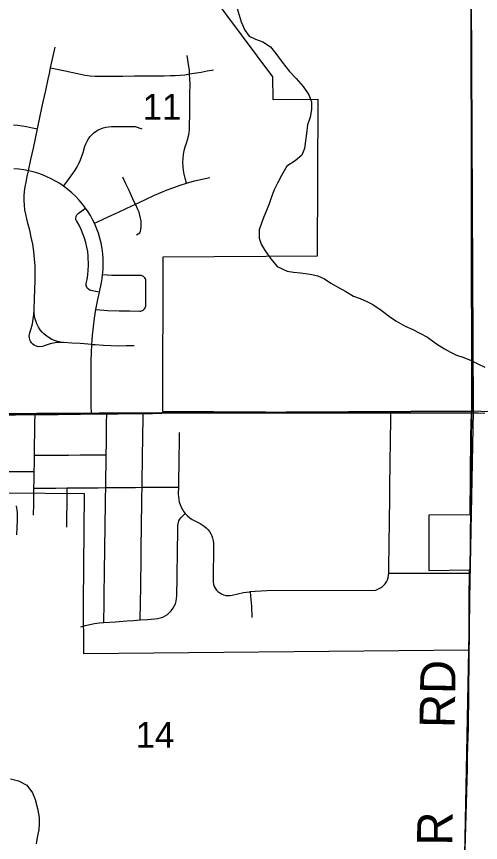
# Model space of a CAD drawing. Extents: x -11.1 to 34, y -3.9 to 22.
# Drawn here: x 5.641 to 6.389, y 15.573 to 16.906 of the extents above; entities that cross this region are included whole.
import ezdxf

# ---------------------------------------------------------------- set-up
doc = ezdxf.new("R2010")
doc.units = 0
for name, color, linetype in [('GM_X_City_Street', 7, 'Continuous'), ('GM_X_Corporation', 7, 'Continuous'), ('GM_X_Minor_River', 7, 'Continuous'), ('GM_X_Section_Text', 7, 'Continuous'), ('GM_X_State_Route', 7, 'Continuous'), ('GM_X_Township_Road', 7, 'Continuous'), ('GM_X_Township_Road_Text', 7, 'Continuous')]:
    doc.layers.add(name, color=color, linetype=linetype)

msp = doc.modelspace()

# ---------------------------------------------------------------- linework, layer by layer
at = {"layer": 'GM_X_City_Street'}
for points in [[(5.7623, 16.3768), (5.7437, 16.3781), (5.7302, 16.379), (5.7166, 16.3799), (5.7118, 16.3805), (5.707, 16.3815), (5.7023, 16.383), (5.6978, 16.3849), (5.6935, 16.3872), (5.6895, 16.39), (5.6857, 16.3931), (5.6823, 16.3965), (5.6792, 16.4003), (5.6765, 16.4044), (5.6742, 16.4087), (5.6723, 16.4132), (5.6708, 16.4179), (5.6698, 16.4226), (5.6693, 16.4275), (5.6692, 16.4324), (5.6699, 16.451), (5.6704, 16.4656), (5.6709, 16.4802), (5.6711, 16.4919), (5.6708, 16.5036), (5.67, 16.5152), (5.6687, 16.5269), (5.667, 16.5384), (5.6647, 16.5499), (5.6621, 16.5613), (5.6597, 16.5705), (5.6573, 16.5797), (5.6557, 16.5869), (5.6545, 16.5943), (5.6537, 16.6017), (5.6533, 16.6091), (5.6534, 16.6165), (5.6539, 16.6239), (5.6548, 16.6313), (5.6562, 16.6386), (5.6582, 16.6479), (5.6602, 16.6572), (5.6641, 16.6754), (5.668, 16.6936), (5.6713, 16.7092), (5.6747, 16.7247), (5.6786, 16.743), (5.6814, 16.7558), (5.6841, 16.7685), (5.688, 16.7868), (5.692, 16.805), (5.694, 16.8142), (5.6959, 16.8235), (5.6995, 16.84), (5.7031, 16.8566)], [(5.9152, 16.6371), (5.9131, 16.6451), (5.9115, 16.6514), (5.9104, 16.6577), (5.9096, 16.6641), (5.9094, 16.6705), (5.9096, 16.6769), (5.9103, 16.6833), (5.9114, 16.6896), (5.913, 16.6958), (5.915, 16.7019), (5.9168, 16.7073), (5.9183, 16.7128), (5.9193, 16.7184), (5.9199, 16.724), (5.9202, 16.7297), (5.9204, 16.7484), (5.9205, 16.767), (5.9207, 16.782), (5.9208, 16.7969), (5.9207, 16.8052), (5.9202, 16.8134), (5.9197, 16.8194), (5.9189, 16.8253), (5.9164, 16.8433)], [(5.6959, 16.8235), (5.7013, 16.8223), (5.7196, 16.8184), (5.7318, 16.8157), (5.7441, 16.8131), (5.7518, 16.8117), (5.7596, 16.8106), (5.7675, 16.81), (5.7753, 16.8099), (5.794, 16.81), (5.8126, 16.8101), (5.8313, 16.8103), (5.8499, 16.8104), (5.8685, 16.8105), (5.8788, 16.8106), (5.8892, 16.8107), (5.897, 16.8109), (5.9047, 16.8114), (5.9125, 16.8122), (5.9202, 16.8134), (5.9386, 16.8165), (5.9486, 16.8182), (5.9586, 16.8198)], [(5.636, 16.7312), (5.6431, 16.7307), (5.6501, 16.7298), (5.657, 16.7286), (5.6664, 16.7265), (5.6747, 16.7247)], [(5.7169, 16.632), (5.722, 16.6391), (5.7318, 16.6528), (5.7353, 16.658), (5.7385, 16.6634), (5.7414, 16.6689), (5.744, 16.6746), (5.7463, 16.6805), (5.7482, 16.6864), (5.7513, 16.6966), (5.7527, 16.7007), (5.7546, 16.7047), (5.7568, 16.7085), (5.7594, 16.712), (5.7623, 16.7153), (5.7656, 16.7182), (5.7691, 16.7209), (5.7728, 16.7231), (5.7768, 16.725), (5.7809, 16.7265), (5.7852, 16.7276), (5.7895, 16.7283), (5.7939, 16.7286), (5.8125, 16.7287), (5.8225, 16.7288), (5.8325, 16.7288), (5.8432, 16.7247)], [(5.7616, 16.2645), (5.7615, 16.2788), (5.7614, 16.2974), (5.7613, 16.3161), (5.7612, 16.3264), (5.7611, 16.3367), (5.7612, 16.3501), (5.7616, 16.3635), (5.7623, 16.3768), (5.7634, 16.391), (5.7649, 16.4052), (5.7668, 16.4193), (5.769, 16.4331), (5.7721, 16.4492), (5.7745, 16.4612), (5.7778, 16.477), (5.7789, 16.4831), (5.7797, 16.4889), (5.7805, 16.4977), (5.7809, 16.5062), (5.7807, 16.5147), (5.7801, 16.5232), (5.779, 16.5316), (5.7774, 16.54), (5.7754, 16.5483), (5.7729, 16.5564), (5.77, 16.5644), (5.7666, 16.5723), (5.7634, 16.5786), (5.76, 16.5848), (5.7563, 16.5909), (5.7523, 16.5968), (5.7472, 16.6034), (5.7418, 16.6098), (5.7361, 16.6159), (5.73, 16.6216), (5.7236, 16.627), (5.7169, 16.632), (5.7105, 16.6364), (5.7038, 16.6405), (5.6969, 16.6442), (5.6898, 16.6475), (5.6826, 16.6505), (5.6752, 16.6531), (5.6678, 16.6553), (5.6602, 16.6572), (5.6524, 16.6586), (5.6445, 16.6597), (5.6366, 16.6603)], [(5.7666, 16.5723), (5.7716, 16.5746), (5.7885, 16.5825), (5.8054, 16.5903), (5.819, 16.5967), (5.8327, 16.6031), (5.8481, 16.6103), (5.8636, 16.6175), (5.8737, 16.622), (5.884, 16.6263), (5.8944, 16.6302), (5.9049, 16.6339), (5.9152, 16.6371), (5.9278, 16.6407), (5.9402, 16.6438), (5.9527, 16.6464)], [(5.8327, 16.6031), (5.8303, 16.6082), (5.8224, 16.6251), (5.8173, 16.636), (5.8123, 16.6468)], [(5.8346, 16.5539), (5.8397, 16.5567), (5.8409, 16.5597), (5.8413, 16.5617), (5.8419, 16.5665), (5.842, 16.5713), (5.8417, 16.5761), (5.8411, 16.5808), (5.84, 16.5855), (5.8385, 16.5901), (5.8367, 16.5945), (5.8327, 16.6031)], [(5.7745, 16.4612), (5.7663, 16.4629), (5.7606, 16.4641), (5.759, 16.4646), (5.7576, 16.4653), (5.7562, 16.4663), (5.7551, 16.4675), (5.7542, 16.4689), (5.7535, 16.4704), (5.7532, 16.472), (5.7531, 16.4736), (5.7533, 16.4753), (5.7546, 16.4818), (5.7559, 16.4892), (5.7567, 16.4966), (5.7572, 16.5041), (5.7567, 16.5191), (5.7558, 16.5266), (5.7545, 16.5339), (5.7528, 16.5412), (5.7506, 16.5484), (5.748, 16.5555), (5.7451, 16.5624), (5.7417, 16.5691), (5.7379, 16.5756), (5.7372, 16.577), (5.7367, 16.5785), (5.7365, 16.5801), (5.7369, 16.5832), (5.7375, 16.5847), (5.7383, 16.5861), (5.7393, 16.5873), (5.7405, 16.5883), (5.7484, 16.594), (5.7523, 16.5968)], [(5.769, 16.4331), (5.7753, 16.4325), (5.7816, 16.4319), (5.7879, 16.4316), (5.8065, 16.4312), (5.8231, 16.4309), (5.8397, 16.4306), (5.8412, 16.4307), (5.8427, 16.431), (5.8441, 16.4316), (5.8454, 16.4323), (5.8465, 16.4333), (5.8475, 16.4344), (5.8483, 16.4357), (5.8489, 16.437), (5.8493, 16.4385), (5.8494, 16.44), (5.8496, 16.4586), (5.8496, 16.4686), (5.8497, 16.4786), (5.8496, 16.4801), (5.8493, 16.4815), (5.8487, 16.4829), (5.8479, 16.4842), (5.847, 16.4853), (5.8458, 16.4863), (5.8446, 16.4871), (5.8432, 16.4877), (5.8417, 16.488), (5.8402, 16.4881), (5.8216, 16.488), (5.8021, 16.4879), (5.7947, 16.488), (5.7872, 16.4884), (5.7797, 16.4889)], [(5.7166, 16.3799), (5.7113, 16.38), (5.706, 16.3798), (5.7007, 16.379), (5.6954, 16.3779), (5.6903, 16.3763), (5.6854, 16.3744), (5.6827, 16.3735), (5.6771, 16.373), (5.6743, 16.3734), (5.6717, 16.3744), (5.6692, 16.3757), (5.667, 16.3774), (5.665, 16.3795), (5.6635, 16.3819), (5.6624, 16.3844), (5.6617, 16.3872), (5.6614, 16.39), (5.6617, 16.3928), (5.6624, 16.3955), (5.6646, 16.4027), (5.6664, 16.41), (5.6678, 16.4174), (5.6687, 16.4249), (5.6692, 16.4324)], [(5.7623, 16.3768), (5.7679, 16.3765), (5.7812, 16.3756), (5.7936, 16.3749), (5.806, 16.3746), (5.8184, 16.3749), (5.8308, 16.3751)], [(5.6698, 16.1978), (5.67, 16.2164), (5.6703, 16.2329), (5.6705, 16.2494), (5.6707, 16.2636)], [(5.7817, 15.928), (5.7818, 15.9373), (5.782, 15.9501), (5.7822, 15.9628), (5.7824, 15.9815), (5.7827, 16.0001), (5.783, 16.0187), (5.7832, 16.0374), (5.7835, 16.056), (5.7838, 16.0747), (5.784, 16.0933), (5.7843, 16.112), (5.7845, 16.1288), (5.7848, 16.1456), (5.785, 16.1643), (5.7853, 16.1815), (5.7855, 16.1986), (5.7858, 16.2173), (5.786, 16.2335), (5.7862, 16.2497), (5.7864, 16.2647)], [(5.8405, 15.932), (5.8406, 15.9402), (5.8407, 15.9517), (5.8409, 15.9633), (5.8412, 15.9819), (5.8414, 16.0005), (5.8417, 16.0192), (5.842, 16.0378), (5.8422, 16.0565), (5.8425, 16.0751), (5.8427, 16.0937), (5.843, 16.1124), (5.8432, 16.1292), (5.8435, 16.1461), (5.8437, 16.1647), (5.844, 16.1834), (5.8443, 16.202), (5.8445, 16.2206), (5.8447, 16.2355), (5.845, 16.2504), (5.8452, 16.2653)], [(5.9033, 16.2344), (5.903, 16.2157), (5.9027, 16.1977), (5.9025, 16.1796), (5.9022, 16.163), (5.902, 16.1464), (5.9018, 16.1351), (5.902, 16.1308), (5.9025, 16.1265), (5.9034, 16.1223), (5.9047, 16.1182), (5.9063, 16.1142), (5.9084, 16.1104), (5.9107, 16.1068), (5.913, 16.1039), (5.9167, 16.1), (5.9203, 16.0969), (5.9242, 16.0942), (5.9284, 16.0918), (5.9369, 16.0877), (5.9405, 16.0857), (5.9438, 16.0834), (5.9468, 16.0808), (5.9496, 16.0779), (5.9521, 16.0747), (5.9542, 16.0712), (5.9559, 16.0676), (5.9573, 16.0638), (5.9582, 16.0598), (5.9588, 16.0558), (5.9589, 16.0518), (5.9586, 16.0332), (5.9582, 16.0148), (5.9579, 15.9964), (5.9581, 15.993), (5.9587, 15.9895), (5.9599, 15.9862), (5.9615, 15.9831), (5.9635, 15.9803), (5.9659, 15.9778), (5.9687, 15.9756), (5.9717, 15.9739), (5.9749, 15.9726), (5.9783, 15.9717), (5.9818, 15.9714), (5.9853, 15.9715), (5.9887, 15.9722), (5.9979, 15.9743), (6.0072, 15.9761), (6.0165, 15.9775), (6.0181, 15.9777), (6.026, 15.9785), (6.0354, 15.9791), (6.0448, 15.9793), (6.2204, 15.9803), (6.2239, 15.9815), (6.2272, 15.9831), (6.2303, 15.9851), (6.2331, 15.9875), (6.2355, 15.9903), (6.2376, 15.9933), (6.2392, 15.9966), (6.2405, 16.0001), (6.2412, 16.0037), (6.2415, 16.0075), (6.2417, 16.0262), (6.242, 16.0448), (6.2422, 16.0635), (6.2424, 16.0821), (6.2427, 16.1007), (6.2429, 16.1194), (6.2431, 16.138), (6.2434, 16.1567), (6.2436, 16.1753), (6.2438, 16.194), (6.2441, 16.2126), (6.2443, 16.2312), (6.2445, 16.2457), (6.2446, 16.2602), (6.2447, 16.2663)], [(5.6694, 16.1718), (5.6696, 16.1848), (5.6698, 16.1978)], [(5.6698, 16.1978), (5.6875, 16.1979), (5.7062, 16.198), (5.7248, 16.1982), (5.7434, 16.1983), (5.7578, 16.1984), (5.7721, 16.1985), (5.7855, 16.1986)], [(5.2553, 16.1662), (5.2644, 16.1671), (5.283, 16.1684), (5.3016, 16.1696), (5.3202, 16.1709), (5.3376, 16.1721), (5.355, 16.1733), (5.3728, 16.1743), (5.4256, 16.1744), (5.4406, 16.1745), (5.4943, 16.1746), (5.513, 16.1746), (5.5316, 16.1747), (5.5502, 16.1747), (5.5689, 16.1747), (5.5875, 16.1748), (5.5992, 16.1748), (5.6109, 16.1748), (5.6233, 16.1715), (5.6382, 16.1716), (5.6531, 16.1717), (5.6694, 16.1718)], [(5.6684, 16.101), (5.6687, 16.1197), (5.6689, 16.1322), (5.669, 16.1448), (5.6692, 16.1583), (5.6694, 16.1718)], [(5.669, 16.1448), (5.6861, 16.1449), (5.7045, 16.145), (5.7228, 16.1452), (5.7415, 16.1453), (5.7601, 16.1455), (5.7724, 16.1455), (5.7848, 16.1456), (5.8034, 16.1458), (5.822, 16.1459), (5.8328, 16.146), (5.8435, 16.1461), (5.858, 16.1462), (5.8726, 16.1462), (5.8873, 16.1463), (5.902, 16.1464)], [(5.7219, 16.0817), (5.7222, 16.1003), (5.7224, 16.1178), (5.7227, 16.1352), (5.7228, 16.1452)], [(5.7448, 15.9208), (5.752, 15.923), (5.7593, 15.9248), (5.7667, 15.9262), (5.7742, 15.9273), (5.7817, 15.928), (5.8003, 15.9292), (5.8189, 15.9305), (5.8297, 15.9312), (5.8405, 15.932), (5.8523, 15.9328), (5.8642, 15.9336), (5.8685, 15.9341), (5.8727, 15.9352), (5.8768, 15.9367), (5.8807, 15.9386), (5.8843, 15.941), (5.8876, 15.9438), (5.8906, 15.9469), (5.8932, 15.9504), (5.8954, 15.9542), (5.8971, 15.9581), (5.8984, 15.9623), (5.8992, 15.9665), (5.8995, 15.9709), (5.8996, 15.9765), (5.8999, 15.9951), (5.9001, 16.0138), (5.9004, 16.0324), (5.9007, 16.051), (5.9009, 16.0678), (5.9011, 16.0845), (5.9014, 16.0872), (5.902, 16.0898), (5.9029, 16.0922), (5.9042, 16.0946), (5.9058, 16.0967), (5.9077, 16.0986), (5.913, 16.1039)], [(6.2415, 16.0075), (6.292, 16.0076), (6.3727, 16.0076)], [(6.0209, 15.9358), (6.0207, 15.9542), (6.0202, 15.9599), (6.019, 15.9702), (6.0181, 15.9777)]]:
    msp.add_lwpolyline(points, dxfattribs=at)
at = {"layer": 'GM_X_Corporation'}
for points in [[(5.385, 17.2762), (6.3727, 17.2765), (6.3775, 16.2691), (5.3715, 16.2638)], [(7.3791, 17.2313), (7.364, 16.2758), (7.3634, 16.2255), (6.3775, 16.2691), (6.3727, 17.2765)], [(5.3715, 16.2638), (6.3775, 16.2691), (6.3578, 15.2497), (5.3559, 15.2538)]]:
    msp.add_lwpolyline(points, close=True, dxfattribs=at)
msp.add_lwpolyline([(5.9275, 16.9789), (6.0538, 16.8089), (6.0542, 16.772), (6.1268, 16.7728), (6.1257, 16.5195), (5.8768, 16.5179), (5.8764, 16.2688), (6.3743, 16.2658), (6.3735, 16.2285), (6.3722, 16.1019), (6.3062, 16.1009), (6.3063, 16.0116), (6.3713, 16.0127), (6.3706, 15.962), (6.3705, 15.8833), (5.7496, 15.8773), (5.749, 15.9599), (5.7505, 16.1357), (5.6236, 16.1369)], dxfattribs=at)
at = {"layer": 'GM_X_Minor_River'}
for points in [[(5.9967, 16.9192), (6.0034, 16.8973), (6.0091, 16.8843), (6.0161, 16.8742), (6.0262, 16.8698), (6.0382, 16.8653), (6.0505, 16.8573), (6.059, 16.8465), (6.0696, 16.8325), (6.0814, 16.8174), (6.0921, 16.8061), (6.1031, 16.7929), (6.1126, 16.7797), (6.1169, 16.7682), (6.117, 16.756), (6.1144, 16.7439), (6.1103, 16.7311), (6.1088, 16.7171)], [(6.1088, 16.7171), (6.1073, 16.7057), (6.1055, 16.6932), (6.1014, 16.6823), (6.0906, 16.6731), (6.0771, 16.6643), (6.0683, 16.6493), (6.0619, 16.637), (6.0567, 16.6265), (6.0523, 16.6148), (6.0482, 16.6035), (6.0441, 16.593), (6.0401, 16.5828), (6.036, 16.5723), (6.0323, 16.5617), (6.0324, 16.5484), (6.0355, 16.5384), (6.0421, 16.528), (6.0509, 16.5152), (6.0615, 16.5024), (6.0773, 16.4951), (6.0879, 16.4933), (6.0992, 16.4923), (6.1147, 16.4904), (6.1272, 16.4874), (6.138, 16.4825), (6.1481, 16.4758), (6.1616, 16.4682), (6.1724, 16.4622), (6.1847, 16.4547), (6.1953, 16.451), (6.2058, 16.4462), (6.2159, 16.4413), (6.2293, 16.4322), (6.2427, 16.4216), (6.2528, 16.4149), (6.2677, 16.4065), (6.2805, 16.4009), (6.2917, 16.3952), (6.3037, 16.3885), (6.3186, 16.3778), (6.3313, 16.3699), (6.341, 16.3643), (6.3508, 16.3595), (6.3628, 16.3557), (6.3744, 16.3509), (6.3853, 16.3457), (6.3962, 16.34)], [(5.6405, 16.1164), (5.6417, 16.1057), (5.6421, 16.0935), (5.6415, 16.0814), (5.6408, 16.0696)], [(5.6314, 15.6757), (5.6442, 15.6723), (5.6573, 15.6651), (5.6669, 15.6531), (5.6712, 15.6423), (5.6749, 15.6274), (5.6772, 15.6133), (5.6774, 15.6034), (5.6767, 15.5932), (5.6741, 15.5807), (5.6727, 15.5708)]]:
    msp.add_lwpolyline(points, dxfattribs=at)
at = {"layer": 'GM_X_State_Route'}
for points in [[(5.5354, 16.2623), (5.554, 16.2624), (5.5685, 16.2626), (5.583, 16.2627), (5.6017, 16.2629), (5.6203, 16.2631), (5.639, 16.2633), (5.6548, 16.2634), (5.6707, 16.2636), (5.6894, 16.2638), (5.708, 16.2639), (5.7266, 16.2641), (5.7441, 16.2643), (5.7616, 16.2645), (5.774, 16.2646), (5.7864, 16.2647), (5.8051, 16.2649), (5.8237, 16.2651), (5.8344, 16.2652), (5.8452, 16.2653), (5.8602, 16.2654), (5.8755, 16.2656), (6.2447, 16.2663), (6.3755, 16.2665)], [(6.3755, 16.2665), (6.386, 16.2661), (6.3964, 16.2657)]]:
    msp.add_lwpolyline(points, dxfattribs=at)
at = {"layer": 'GM_X_Township_Road'}
msp.add_line((6.3713, 15.8784), (6.3714, 15.8856), dxfattribs=at)
for points in [[(6.3755, 16.2665), (6.374, 17.2788)], [(6.3737, 16.1013), (6.3739, 16.1199), (6.3741, 16.1385), (6.3743, 16.1572), (6.3745, 16.1758), (6.3747, 16.1945), (6.3749, 16.2131), (6.3751, 16.2317), (6.3753, 16.2491), (6.3755, 16.2665)], [(6.3727, 16.0076), (6.3729, 16.0262), (6.3731, 16.0449), (6.3733, 16.0635), (6.3735, 16.0821), (6.3736, 16.0917), (6.3737, 16.1013)], [(6.3714, 15.8856), (6.3715, 15.897), (6.3717, 15.9157), (6.3719, 15.9343), (6.372, 15.948), (6.3722, 15.9618), (6.3724, 15.9804), (6.3725, 15.9902), (6.3726, 15.9999), (6.3727, 16.0076)], [(6.3647, 15.5613), (6.3652, 15.5799), (6.3657, 15.5985), (6.3662, 15.6172), (6.3667, 15.6358), (6.3672, 15.6544), (6.3677, 15.6731), (6.3682, 15.6917), (6.3687, 15.7103), (6.3692, 15.729), (6.3696, 15.7435), (6.37, 15.7581), (6.3702, 15.7768), (6.3704, 15.7954), (6.3706, 15.814), (6.3708, 15.8327), (6.371, 15.8513), (6.3711, 15.8649), (6.3713, 15.8784)]]:
    msp.add_lwpolyline(points, dxfattribs=at)

# ---------------------------------------------------------------- texts
at = {"layer": 'GM_X_Section_Text'}
for s, p in [('11', (5.8444, 16.7394)), ('14', (5.8331, 15.7256))]:
    msp.add_text(s, height=0.04186, rotation=0, dxfattribs=at).set_placement(p)
at = {"layer": 'GM_X_Township_Road_Text'}
for s, height, rotation, p in [('RD', 0.05682, 89.0118, (6.3477, 15.7572)), ('R', 0.0568, 89.4159, (6.3438, 15.5675))]:
    msp.add_text(s, height=height, rotation=rotation, dxfattribs=at).set_placement(p)

doc.saveas('drawing.dxf')
